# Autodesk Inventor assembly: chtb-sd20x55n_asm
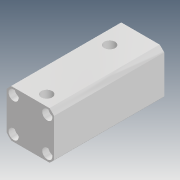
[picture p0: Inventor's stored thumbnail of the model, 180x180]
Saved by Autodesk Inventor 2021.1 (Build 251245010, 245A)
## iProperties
Company: Microsoft
Created: 2018-04
Part Number: chtb-sd20x55n_asm
Description: STEP AP214
Document SubType Name: Assembly
Designer: user
Title: chtb-sd20x55n_asm.STEP
Author: Windows
Revision Number: ÈÎºÎ
Sending System: SolidWorks 2015
Preprocessor: SwSTEP 2.0
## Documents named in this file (4)
- D:\Vault_2016\Projekty\Clamptek\Hydraulic\CHTB\CHTB-20\Inventor\CHTB-SD20x55N\chtb-sd20x55n_asm.iam
- D:\Vault_2016\Projekty\Clamptek\Hydraulic\CHTB\CHTB-20\Inventor\CHTB-SD20x55N\CHTB-SD20X55NBT.ipt
- D:\Vault_2016\Projekty\Clamptek\Hydraulic\CHTB\CHTB-20\Inventor\CHTB-SD20x55N\QG.ipt
- D:\Vault_2016\Projekty\Clamptek\Hydraulic\CHTB\CHTB-20\Inventor\CHTB-SD20x55N\CHTB-SD20X55NHSG.ipt
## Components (3 placed, 3 different names)
1. CHTB-SD20X55NBT_1
2. QG_2
3. CHTB-SD20X55NHSG_3
